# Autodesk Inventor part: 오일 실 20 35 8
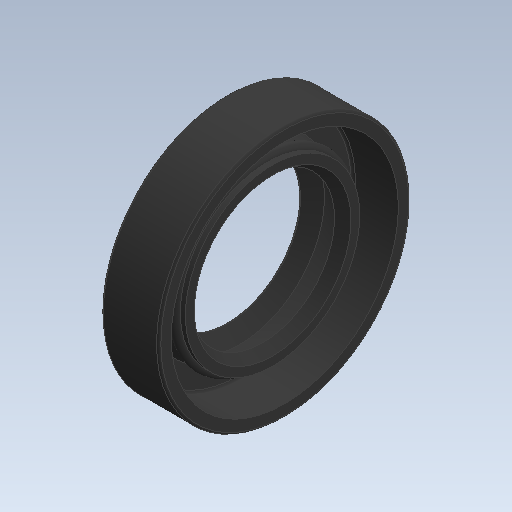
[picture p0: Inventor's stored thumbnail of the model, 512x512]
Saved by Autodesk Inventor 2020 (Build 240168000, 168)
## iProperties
Created: 2024-09
Part Number: 오일 실 20 35 8
Material: 고무
Description: 오일-실
Document SubType Name: Modeling
Designer: oem
Density: 0.93 g/cm^3
Appearance: 기본값
Author: jhkim
Sending System: Autodesk Inventor 2025
Preprocessor: ST-DEVELOPER v20
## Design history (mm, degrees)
feature "Solid1"
node "솔리드1"
